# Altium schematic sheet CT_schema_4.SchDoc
size 451 x 443 mm
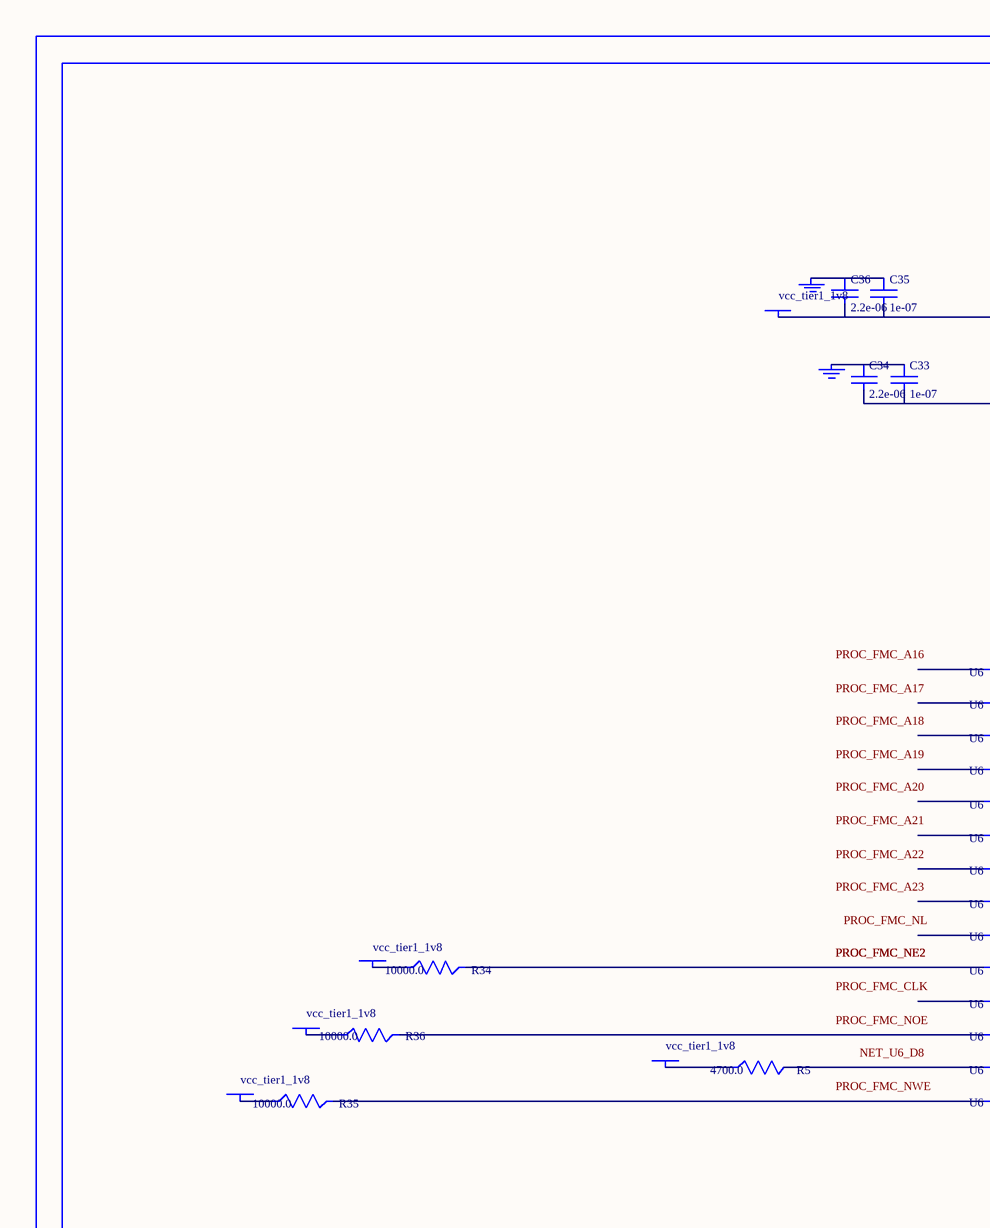
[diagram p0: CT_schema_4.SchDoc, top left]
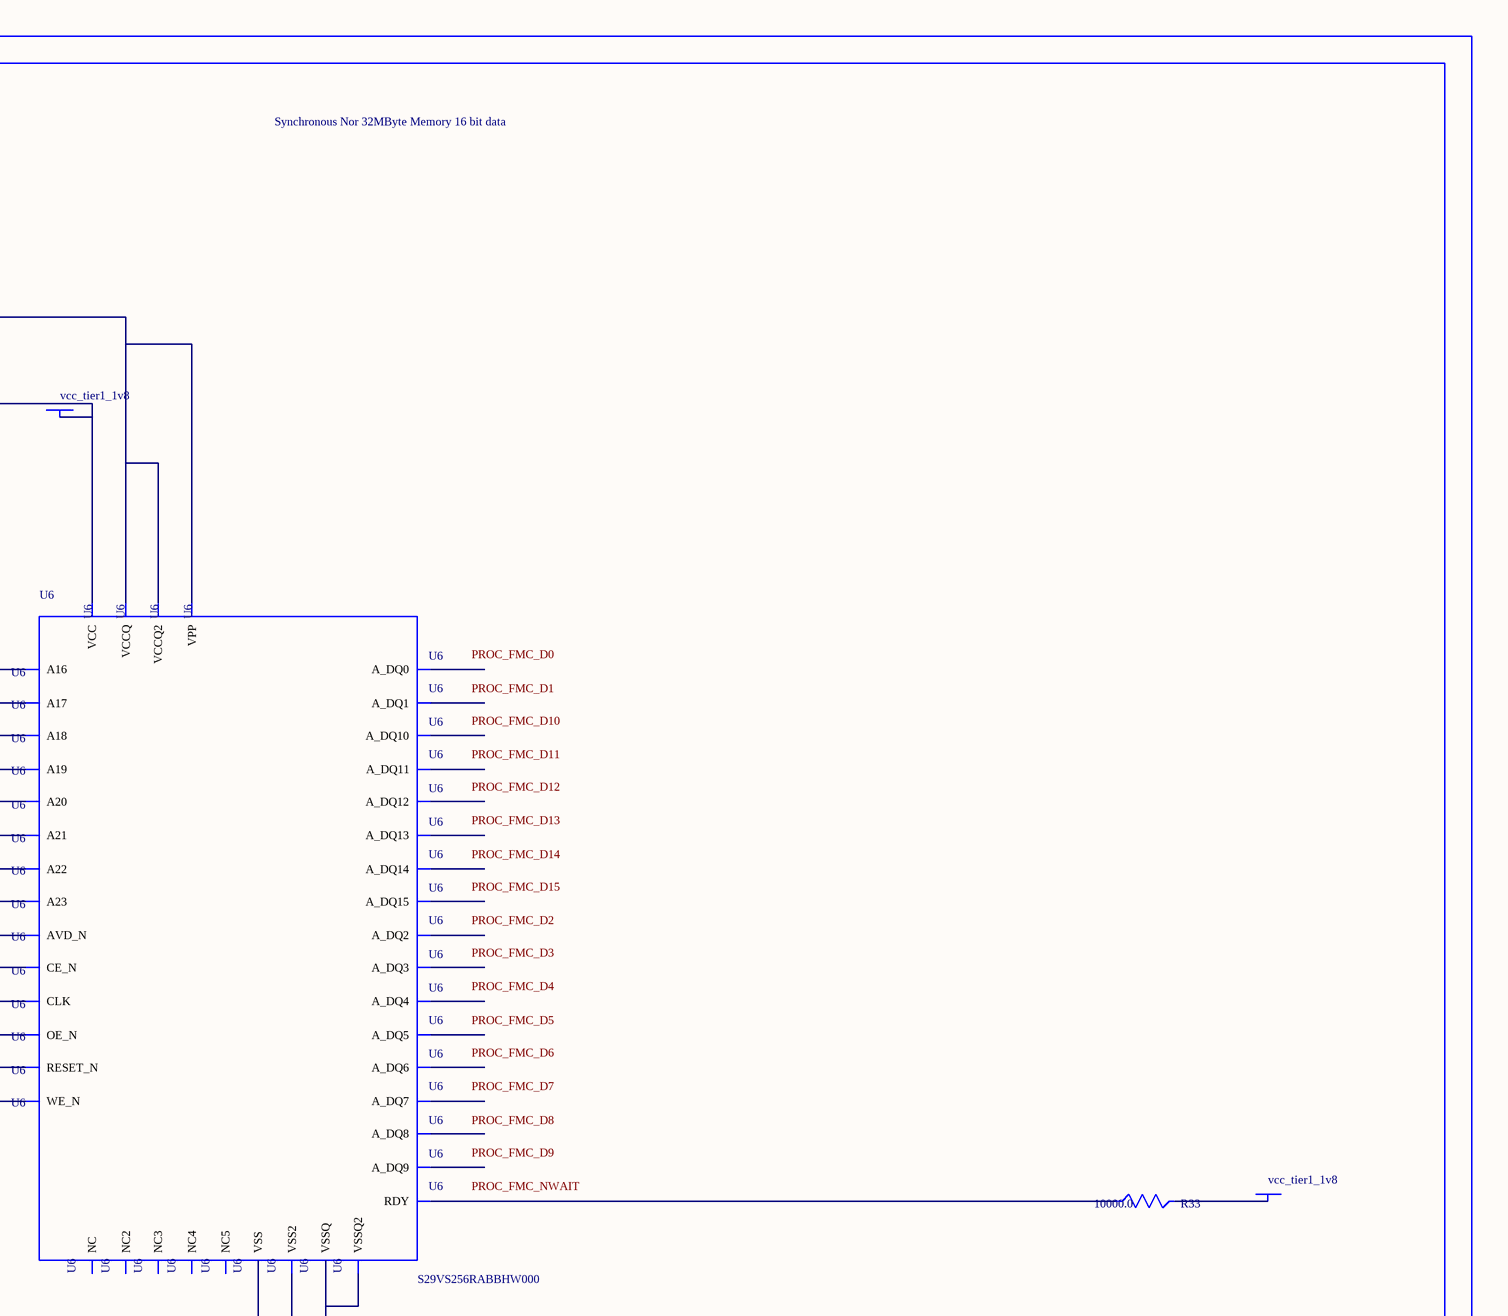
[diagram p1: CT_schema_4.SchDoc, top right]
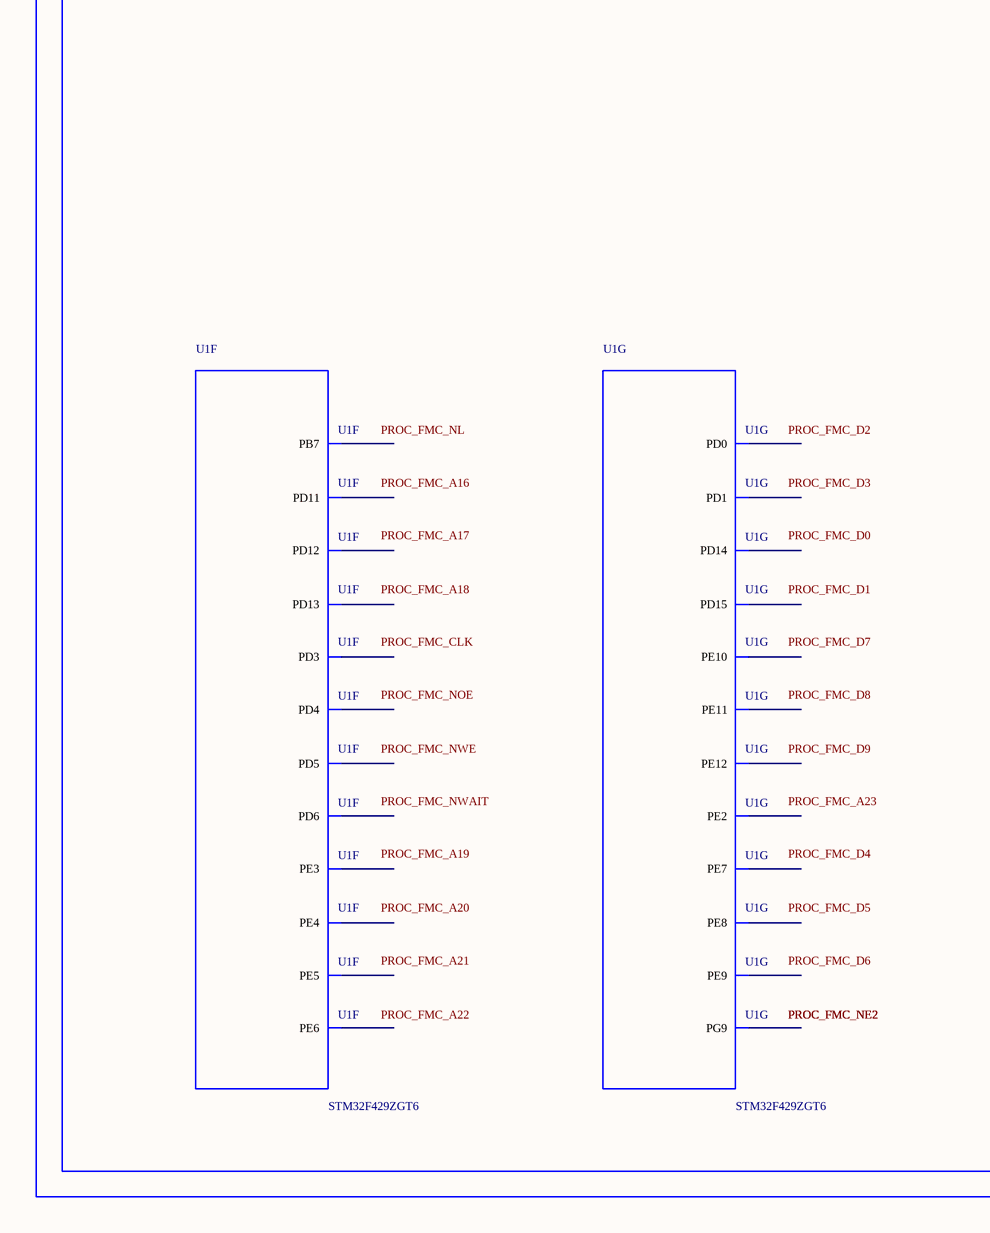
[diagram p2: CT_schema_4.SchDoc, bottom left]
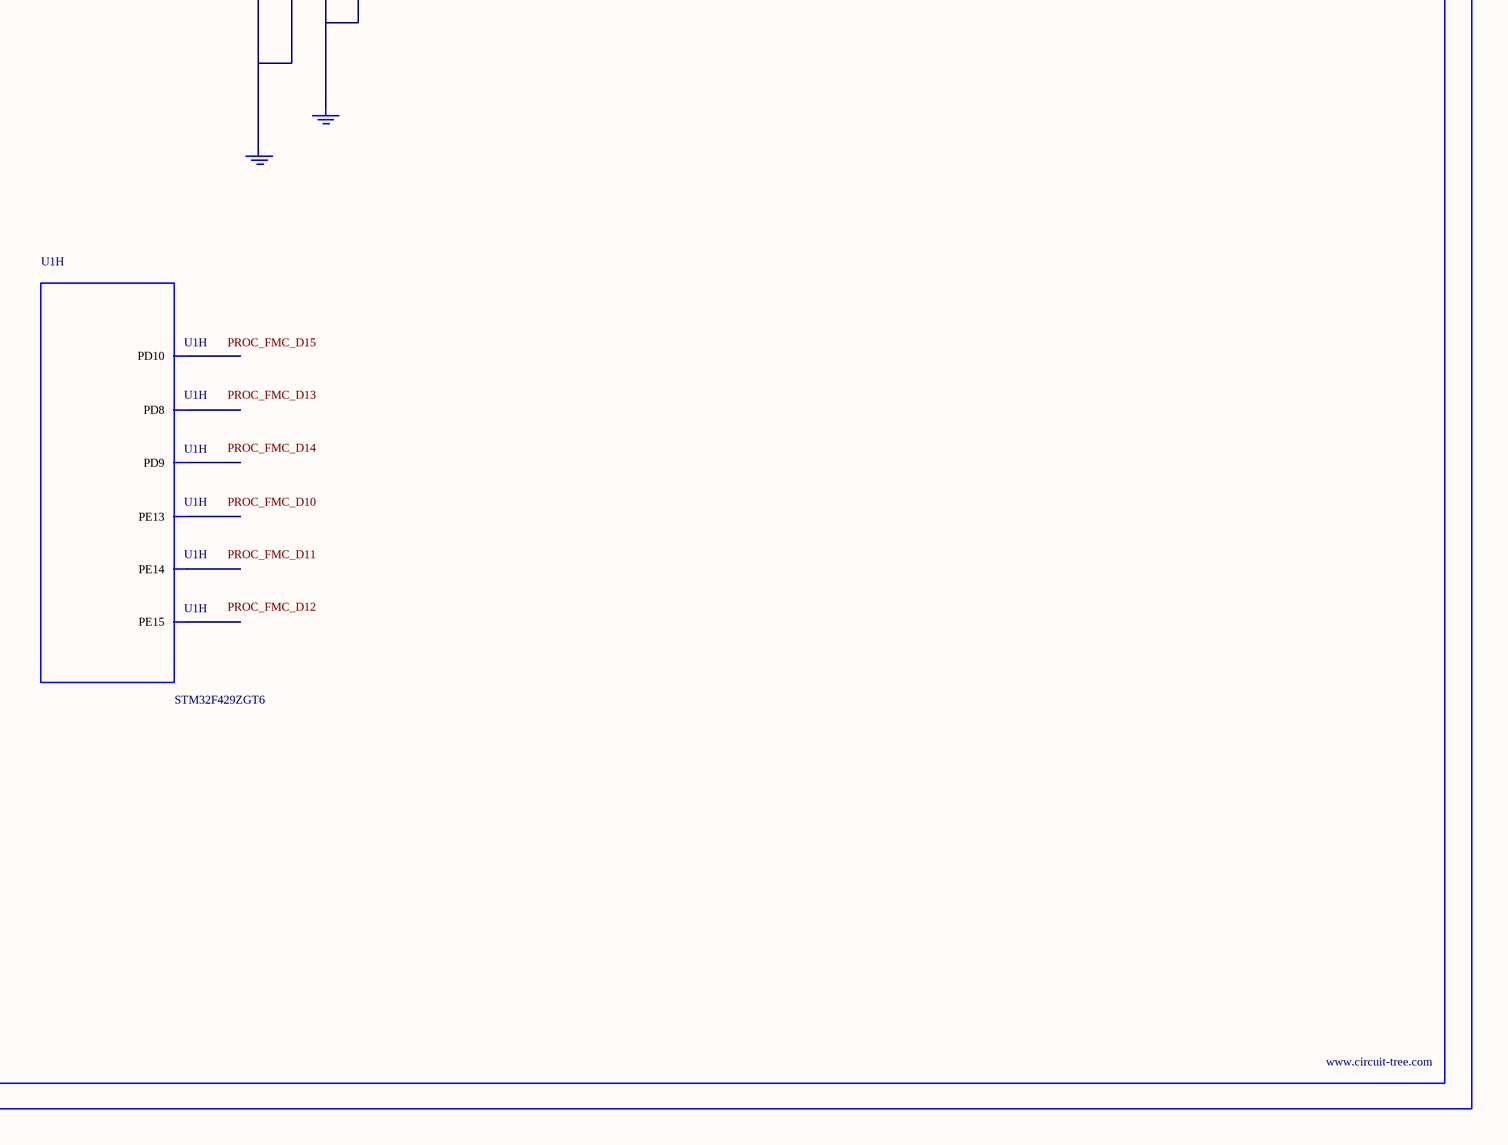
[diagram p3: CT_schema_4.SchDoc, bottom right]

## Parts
BORDER3  (no value)
C33  1e-07  [C0402]
C34  2.2e-06  [C0603]
C35  1e-07  [C0402]
C36  2.2e-06  [C0603]
GND_INSTANCE_3_0  (no value)
GND_INSTANCE_3_1  (no value)
GND_INSTANCE_3_2  (no value)
GND_INSTANCE_3_3  (no value)
POWER_INSTANCE_3_0  vcc_tier1_1v8
POWER_INSTANCE_3_1  vcc_tier1_1v8
POWER_INSTANCE_3_2  vcc_tier1_1v8
POWER_INSTANCE_3_3  vcc_tier1_1v8
POWER_INSTANCE_3_4  vcc_tier1_1v8
POWER_INSTANCE_3_5  vcc_tier1_1v8
POWER_INSTANCE_3_6  vcc_tier1_1v8
R5  4700.0  [R0603]
R33  10000.0  [R0603]
R34  10000.0  [R0603]
R35  10000.0  [R0603]
R36  10000.0  [R0603]
U1  STM32F429ZGT6  [LQFP144]  (parts F,G,H of 11)
U6  S29VS256RABBHW000  [S29VS256RABBHW000]

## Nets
NetC33_1: C33.1 C34.1 GND_INSTANCE_3_0.0(GND)
NetC33_2: C33.2 C34.2 POWER_INSTANCE_3_0.0(PWR) U6.C7(VCC)
NetC35_1: C35.1 C36.1 GND_INSTANCE_3_1.0(GND)
NetC35_2: C35.2 C36.2 POWER_INSTANCE_3_1.0(PWR) U6.C9(VPP) U6.D3(VCCQ) U6.F10(VCCQ2)
NetGND_INSTANCE_3_2_0: GND_INSTANCE_3_2.0(GND) U6.C5(VSS) U6.D12(VSS2)
NetGND_INSTANCE_3_3_0: GND_INSTANCE_3_3.0(GND) U6.E3(VSSQ) U6.F5(VSSQ2)
NetPOWER_INSTANCE_3_2_0: POWER_INSTANCE_3_2.0(PWR) R33.2
NetPOWER_INSTANCE_3_3_0: POWER_INSTANCE_3_3.0(PWR) R34.1
NetPOWER_INSTANCE_3_4_0: POWER_INSTANCE_3_4.0(PWR) R35.1
NetPOWER_INSTANCE_3_5_0: POWER_INSTANCE_3_5.0(PWR) R36.1
NetPOWER_INSTANCE_3_6_0: POWER_INSTANCE_3_6.0(PWR) R5.1
NetR5_2: R5.2 U6.D8(RESET_N)
NetR33_1: R33.1 U6.C3(RDY)
NetR34_2: R34.2 U6.D11(CE_N)
NetR35_2: R35.2 U6.C8(WE_N)
NetR36_2: R36.2 U6.E12(OE_N)

Not connected (* = marked no-connect by the designer): U1 1(PE2) 2(PE3) 3(PE4) 4(PE5) 5(PE6) 58(PE7) 59(PE8) 60(PE9) 63(PE10) 64(PE11) 65(PE12) 66(PE13) 67(PE14) 68(PE15) 77(PD8) 78(PD9) 79(PD10) 80(PD11) 81(PD12) 82(PD13) 85(PD14) 86(PD15) 114(PD0) 115(PD1) 117(PD3) 118(PD4) 119(PD5) 122(PD6) 124(PG9) 137(PB7); U6 A1(NC) A14(NC2) C4(A21) C6(CLK) C10(A19) C11(A17) C12(A22) D4(A16) D5(A20) D6(AVD_N) D7(A23) D9(NC3) D10(A18) E4(A_DQ8) E5(A_DQ9) E6(A_DQ2) E7(A_DQ3) E8(A_DQ12) E9(A_DQ13) E10(A_DQ6) E11(A_DQ7) F3(A_DQ0) F4(A_DQ1) F6(A_DQ10) F7(A_DQ11) F8(A_DQ4) F9(A_DQ5) F11(A_DQ14) F12(A_DQ15) H1(NC4) H14(NC5)

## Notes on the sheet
- Labels drawn without touching a wire or pin: NET_U6_D8, PROC_FMC_A16, PROC_FMC_A17, PROC_FMC_A18, PROC_FMC_A19, PROC_FMC_A20, PROC_FMC_A21, PROC_FMC_A22, PROC_FMC_A23, PROC_FMC_CLK, PROC_FMC_D0, PROC_FMC_D1, PROC_FMC_D2, PROC_FMC_D3, PROC_FMC_D4, PROC_FMC_D5, PROC_FMC_D6, PROC_FMC_D7, PROC_FMC_D8, PROC_FMC_D9, PROC_FMC_D10, PROC_FMC_D11, PROC_FMC_D12, PROC_FMC_D13, PROC_FMC_D14, PROC_FMC_D15, PROC_FMC_NL, PROC_FMC_NOE, PROC_FMC_NWAIT, PROC_FMC_NWE

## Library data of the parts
BORDER3 = BORDER_PAGE3
C33 C35 = C0402C104K3RACTU
C34 C36 = C0603C225K8RACTU
GND_INSTANCE_3_0-GND_INSTANCE_3_3 = GND
POWER_INSTANCE_3_0-POWER_INSTANCE_3_6 = PWR
R5 = RC0603JR-074K7L
R33-R36 = RC0603JR-0710KL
